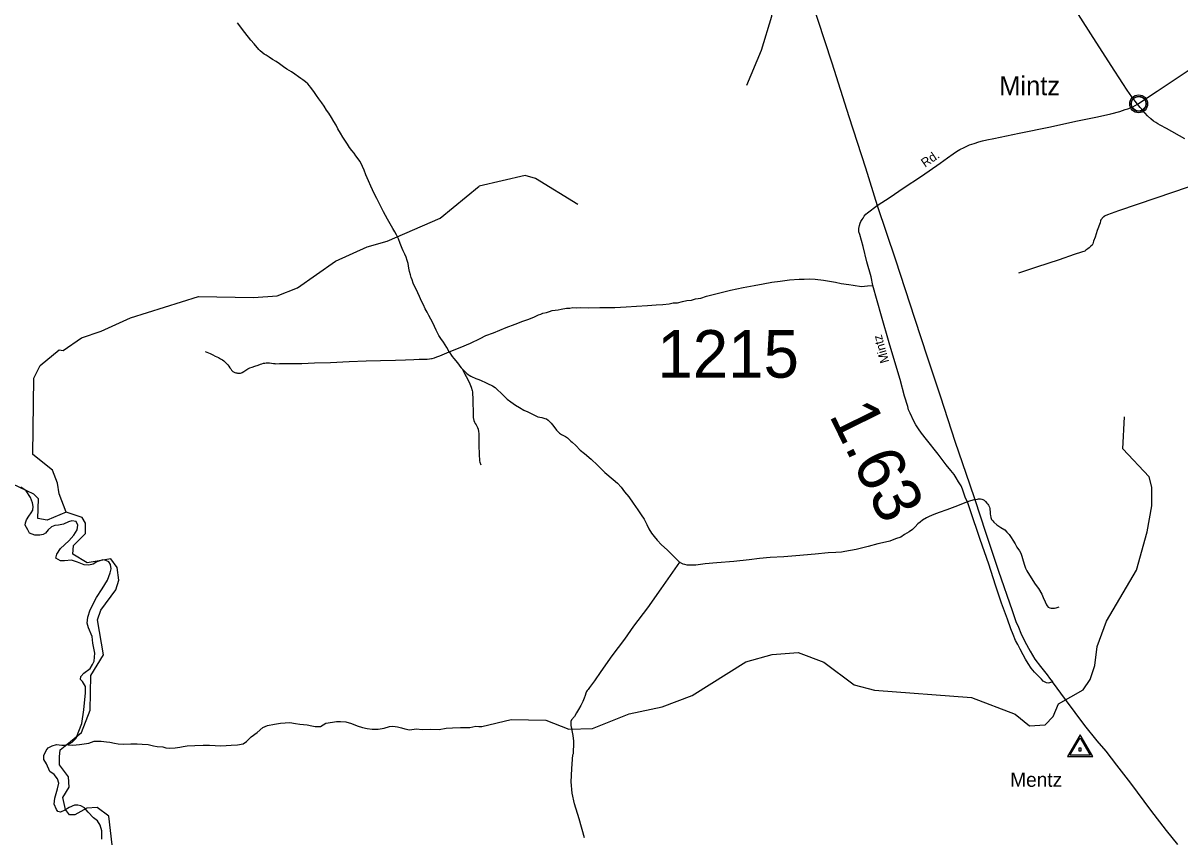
# Model space of a CAD drawing. Extents: x 2093524 to 2270757, y 289120 to 570408.
# Drawn here: x 2145218 to 2157372, y 409015 to 417566 of the extents above; entities that cross this region are included whole.
import ezdxf

# ---------------------------------------------------------------- set-up
doc = ezdxf.new("R2010")
doc.units = 0
for name, color, linetype in [('Exist Boundary Political CountyLine', 7, 'Continuous'), ('Exist Civil Demographics Community CELL', 7, 'Continuous'), ('Exist Civil Demographics Community Label', 7, 'Continuous'), ('Exist Hydrographic Creek Single Shore', 7, 'Continuous'), ('Exist Hydrographic Misc Water Feature', 7, 'Continuous'), ('Exist Road Non-System Type 51', 7, 'Continuous'), ('Exist Road Primary NC Attributed', 7, 'Continuous'), ('Exist Road Secondary Mileage Hundredths English Label', 7, 'Continuous'), ('Exist Road Secondary Type 51 Attributed', 7, 'Continuous'), ('Exist Road Secondary Type 51 Label', 7, 'Continuous'), ('Exist Road Secondary Type 51 Number Label', 7, 'Continuous'), ('Exist Survey Geodetic Marker CELL', 7, 'Continuous'), ('Exist Survey Geodetic Marker Label', 7, 'Continuous'), ('Exist Utilities Telephone Line', 7, 'Continuous')]:
    doc.layers.add(name, color=color, linetype=linetype)

msp = doc.modelspace()

# ---------------------------------------------------------------- linework, layer by layer
at = {"layer": 'Exist Boundary Political CountyLine'}
for points in [[(2145998, 409182), (2145957, 409214), (2145900, 409276), (2145863, 409319), (2145824, 409341), (2145792, 409347), (2145758, 409347), (2145702, 409324), (2145657, 409294), (2145612, 409274), (2145584, 409281), (2145568, 409304), (2145545, 409360), (2145551, 409423), (2145580, 409521), (2145592, 409581), (2145579, 409624), (2145545, 409672), (2145500, 409701), (2145464, 409783), (2145434, 409828), (2145434, 409869), (2145460, 409921), (2145480, 409950), (2145524, 409972), (2145568, 409985), (2145623, 409978), (2145658, 409980), (2145700, 409991), (2145733, 410011), (2145774, 410051), (2145804, 410127), (2145836, 410208), (2145855, 410350), (2145875, 410530), (2145875, 410594), (2145840, 410648), (2145821, 410669), (2145823, 410699), (2145857, 410734), (2145922, 410785), (2145948, 410826), (2145963, 410863), (2145971, 410944), (2145949, 411049), (2145944, 411122), (2145906, 411210), (2145890, 411262), (2145899, 411324), (2145921, 411401), (2145990, 411532), (2146048, 411620), (2146103, 411713), (2146134, 411788), (2146142, 411833), (2146136, 411876), (2146120, 411906), (2146088, 411919), (2146054, 411925), (2145992, 411906), (2145953, 411882), (2145910, 411869), (2145858, 411873), (2145788, 411901), (2145726, 411923), (2145654, 411917), (2145610, 411917), (2145562, 411944), (2145571, 411985), (2145612, 412045), (2145698, 412125), (2145752, 412185), (2145786, 412241), (2145793, 412290), (2145774, 412328), (2145728, 412335), (2145696, 412324), (2145643, 412301), (2145589, 412292), (2145552, 412288), (2145516, 412273), (2145482, 412240), (2145452, 412208), (2145428, 412191), (2145394, 412185), (2145340, 412187), (2145284, 412208), (2145269, 412243), (2145239, 412290), (2145243, 412316), (2145254, 412348), (2145278, 412384), (2145303, 412419), (2145320, 412447), (2145322, 412485), (2145318, 412526), (2145295, 412582), (2145250, 412650), (2145193, 412691)], [(2146046, 408991), (2146045, 409079), (2146026, 409139), (2145998, 409182)]]:
    msp.add_lwpolyline(points, dxfattribs=at)
at = {"layer": 'Exist Civil Demographics Community CELL'}
msp.add_lwpolyline([(2156862, 416730), (2156863, 416736), (2156864, 416742), (2156867, 416750), (2156870, 416755), (2156874, 416761), (2156877, 416766), (2156881, 416771), (2156886, 416775), (2156891, 416780), (2156897, 416783), (2156902, 416786), (2156907, 416789), (2156912, 416791), (2156918, 416793), (2156922, 416794), (2156927, 416795), (2156931, 416795), (2156938, 416796), (2156942, 416796), (2156948, 416795), (2156953, 416795), (2156957, 416794), (2156962, 416792), (2156968, 416790), (2156974, 416787), (2156981, 416784), (2156986, 416780), (2156991, 416776), (2156994, 416773), (2156998, 416769), (2157002, 416764), (2157005, 416759), (2157008, 416754), (2157011, 416749), (2157013, 416744), (2157014, 416739), (2157016, 416735), (2157017, 416729), (2157017, 416724), (2157018, 416718), (2157017, 416712), (2157017, 416706), (2157016, 416701), (2157014, 416695), (2157012, 416689), (2157010, 416684), (2157007, 416678), (2157004, 416673), (2157000, 416668), (2156996, 416663), (2156991, 416658), (2156986, 416654), (2156981, 416651), (2156976, 416648), (2156969, 416645), (2156962, 416642), (2156956, 416641), (2156950, 416639), (2156945, 416639), (2156941, 416639), (2156935, 416639), (2156931, 416639), (2156925, 416640), (2156919, 416641), (2156915, 416642), (2156910, 416644), (2156905, 416646), (2156901, 416649), (2156894, 416653), (2156889, 416657), (2156884, 416661), (2156879, 416666), (2156876, 416670), (2156873, 416674), (2156869, 416681), (2156867, 416685), (2156866, 416689), (2156863, 416697), (2156862, 416704), (2156861, 416709), (2156861, 416716), (2156861, 416720), (2156861, 416727)], close=True, dxfattribs=at)
for radius in [94.3, 76.7]:
    msp.add_circle((2156939, 416718), radius, dxfattribs=at)
at = {"layer": 'Exist Hydrographic Creek Single Shore'}
msp.add_line((2145639, 414126), (2145830, 414260), dxfattribs=at)
for points in [[(2152821, 416913), (2152977, 417280), (2153083, 417639), (2153074, 417905), (2153098, 417953), (2153073, 418062), (2152829, 418411), (2152619, 418635), (2152460, 418776), (2152143, 418898), (2152034, 419014), (2152032, 419264), (2151723, 419513), (2151547, 419762), (2151437, 420043), (2151377, 420320), (2151318, 420452), (2151284, 420617), (2151233, 420667), (2151147, 421233), (2151001, 421732), (2150776, 422081), (2150324, 422464), (2149980, 422851)], [(2151045, 415659), (2150602, 415933), (2150494, 415965), (2150010, 415853)], [(2145830, 414260), (2146038, 414328), (2146345, 414470), (2147061, 414692), (2147637, 414683), (2147886, 414701), (2148102, 414786), (2148500, 415063), (2148833, 415214), (2149042, 415275), (2149599, 415517), (2150010, 415853)], [(2145671, 412426), (2145595, 412618), (2145578, 412733), (2145528, 412869), (2145319, 413034), (2145332, 413834), (2145398, 413967), (2145597, 414134), (2145639, 414126)], [(2150036, 410175), (2150347, 410250), (2150709, 410243), (2150952, 410146), (2151201, 410154), (2151584, 410308), (2151933, 410383), (2152249, 410501), (2152813, 410854), (2153088, 410930), (2153363, 410951), (2153630, 410851), (2153948, 410611), (2154165, 410555), (2155181, 410479), (2155641, 410305), (2155791, 410181), (2155958, 410191), (2156041, 410281), (2156098, 410414), (2156355, 410560), (2156430, 410667), (2156479, 410817), (2156503, 411016), (2156601, 411283), (2156915, 411818), (2157029, 412220), (2157078, 412494), (2157077, 412688), (2157051, 412797), (2156774, 413094), (2156789, 413428)], [(2145676, 409984), (2145691, 409983), (2145741, 409980), (2145809, 409987), (2145859, 409991), (2145907, 410000), (2145966, 410019), (2146038, 410022), (2146094, 410014), (2146130, 410009), (2146177, 409999), (2146215, 409994), (2146273, 409990), (2146349, 409991), (2146417, 409992), (2146467, 409989), (2146531, 409984), (2146587, 409970), (2146627, 409965), (2146686, 409960), (2146718, 409952), (2146758, 409946), (2146816, 409951), (2146865, 409956), (2146898, 409966), (2146943, 409973), (2147021, 409976), (2147109, 409977), (2147177, 409980), (2147235, 409974), (2147294, 409971), (2147350, 409976), (2147405, 409977), (2147472, 409983), (2147531, 409992), (2147565, 410017), (2147614, 410065), (2147676, 410110), (2147735, 410163), (2147785, 410187), (2147859, 410200), (2147923, 410211), (2148021, 410216), (2148081, 410207), (2148125, 410200), (2148203, 410191), (2148253, 410183), (2148288, 410174), (2148342, 410176), (2148399, 410209), (2148467, 410222), (2148511, 410226), (2148551, 410227), (2148607, 410224), (2148667, 410206), (2148727, 410181), (2148782, 410164), (2148834, 410152), (2148886, 410147), (2148950, 410148), (2149012, 410157), (2149066, 410175), (2149104, 410180), (2149150, 410170), (2149194, 410159), (2149228, 410149), (2149276, 410140), (2149350, 410149), (2149410, 410144), (2149498, 410145), (2149590, 410144), (2149664, 410157), (2149730, 410162), (2149812, 410165), (2149856, 410165), (2149912, 410164), (2149944, 410172), (2149976, 410179), (2150006, 410175), (2150036, 410175)]]:
    msp.add_lwpolyline(points, dxfattribs=at)
at = {"layer": 'Exist Hydrographic Misc Water Feature'}
for points in [[(2145671, 412426), (2145472, 412342), (2145372, 412360), (2145379, 412567), (2145329, 412617), (2145037, 412757), (2144786, 412929), (2144704, 412947), (2144553, 412888), (2144528, 412856), (2144453, 412864), (2144253, 412979), (2144128, 412910), (2144137, 412627), (2144088, 412560), (2144005, 412502), (2143671, 412601), (2143354, 412774)], [(2145676, 409984), (2145832, 410110), (2145923, 410345), (2145930, 410712), (2146061, 410929), (2146001, 411295), (2146035, 411396), (2146191, 411612), (2146224, 411713), (2146207, 411845), (2146141, 411938), (2145890, 411894), (2145740, 411985), (2145748, 412077), (2145873, 412202), (2145873, 412311), (2145838, 412371), (2145671, 412426)], [(2145601, 409856), (2145607, 409928), (2145676, 409984)], [(2145636, 409429), (2145703, 409539), (2145695, 409647), (2145601, 409771), (2145601, 409856)], [(2149605, 404865), (2149524, 405343), (2149320, 405798), (2149038, 406174), (2148568, 406581), (2147909, 406957), (2147219, 407208), (2146592, 407428), (2146248, 407678), (2146122, 407851), (2146093, 408150), (2146105, 408799), (2146155, 408933), (2146120, 409232), (2145996, 409323), (2145887, 409315), (2145762, 409246), (2145704, 409247), (2145663, 409303), (2145636, 409429)]]:
    msp.add_lwpolyline(points, dxfattribs=at)
at = {"layer": 'Exist Road Non-System Type 51'}
msp.add_line((2155219, 412560), (2155140, 412535), dxfattribs=at)
for points in [[(2149694, 414111), (2149669, 414157), (2149635, 414215), (2149607, 414253), (2149587, 414284), (2149571, 414313), (2149559, 414339), (2149541, 414378), (2149523, 414417), (2149502, 414456), (2149482, 414494), (2149462, 414530), (2149443, 414565), (2149424, 414604), (2149405, 414645), (2149384, 414692), (2149365, 414731), (2149347, 414770), (2149331, 414803), (2149317, 414835), (2149305, 414867), (2149295, 414893), (2149287, 414922), (2149278, 414957), (2149272, 414990), (2149268, 415015), (2149262, 415041), (2149252, 415073), (2149242, 415105), (2149227, 415139), (2149211, 415174), (2149199, 415199), (2149179, 415250), (2149161, 415300), (2149140, 415342), (2149123, 415373), (2149102, 415408), (2149048, 415506), (2149006, 415583), (2148961, 415667), (2148933, 415723), (2148911, 415767), (2148889, 415813), (2148870, 415853), (2148848, 415907), (2148820, 415973), (2148800, 416021), (2148784, 416058), (2148772, 416085), (2148755, 416114), (2148739, 416140), (2148715, 416173), (2148695, 416198), (2148671, 416228), (2148647, 416259), (2148625, 416294), (2148605, 416324), (2148576, 416369), (2148554, 416409), (2148526, 416455), (2148506, 416495), (2148484, 416533), (2148458, 416575), (2148429, 416619), (2148407, 416652), (2148381, 416692), (2148355, 416730), (2148326, 416770), (2148301, 416806), (2148279, 416836), (2148253, 416874), (2148238, 416894), (2148226, 416907), (2148208, 416927), (2148184, 416949), (2148158, 416969), (2148135, 416984), (2148110, 417003), (2148072, 417029), (2148036, 417053), (2147989, 417082), (2147954, 417107), (2147911, 417137), (2147876, 417161), (2147839, 417184), (2147803, 417208), (2147771, 417228), (2147751, 417241), (2147728, 417256), (2147709, 417274), (2147694, 417289), (2147679, 417307), (2147660, 417330), (2147645, 417347), (2147612, 417387), (2147548, 417468), (2147470, 417570)], [(2157799, 415957), (2157121, 415727), (2156728, 415593), (2156612, 415553), (2156586, 415541), (2156576, 415535), (2156574, 415532), (2156568, 415529), (2156542, 415500), (2156538, 415488), (2156533, 415468), (2156503, 415386), (2156481, 415316), (2156466, 415274), (2156456, 415246), (2156450, 415234), (2156434, 415218), (2156420, 415204), (2156406, 415194), (2156384, 415180), (2156372, 415171), (2156340, 415159), (2156261, 415133), (2156103, 415080), (2155865, 415003), (2155676, 414938)], [(2149694, 414111), (2149811, 414156), (2149919, 414202), (2150021, 414253), (2150081, 414282), (2150161, 414313), (2150295, 414367), (2150387, 414402), (2150470, 414434), (2150530, 414455), (2150590, 414481), (2150632, 414499), (2150658, 414509), (2150680, 414518), (2150716, 414526), (2150748, 414534), (2150778, 414546), (2150809, 414550), (2150840, 414552), (2150870, 414559), (2150928, 414569), (2150961, 414571), (2150995, 414577), (2151035, 414575), (2151075, 414576), (2151161, 414574), (2151277, 414579), (2151359, 414579), (2151435, 414578), (2151553, 414586), (2151661, 414591), (2151777, 414598), (2151869, 414604), (2151941, 414608), (2152007, 414617), (2152049, 414625), (2152095, 414627), (2152145, 414640), (2152192, 414650), (2152241, 414656), (2152284, 414667), (2152338, 414677), (2152398, 414695), (2152524, 414728), (2152652, 414761), (2152782, 414787), (2152900, 414808), (2152993, 414826), (2153083, 414845), (2153173, 414856), (2153269, 414868), (2153371, 414877), (2153425, 414877), (2153481, 414879), (2153541, 414877), (2153627, 414866), (2153689, 414854), (2153755, 414845), (2153813, 414829), (2153895, 414819), (2153939, 414814), (2154027, 414798), (2154057, 414801), (2154089, 414805), (2154147, 414809)], [(2147129, 414116), (2147183, 414093), (2147211, 414079), (2147237, 414067), (2147270, 414052), (2147291, 414039), (2147311, 414027), (2147325, 414017), (2147341, 414004), (2147356, 413990), (2147369, 413976), (2147379, 413962), (2147391, 413944), (2147399, 413932), (2147404, 413926), (2147408, 413920), (2147414, 413912), (2147420, 413906), (2147427, 413901), (2147436, 413897), (2147443, 413895), (2147454, 413892), (2147462, 413890), (2147472, 413888), (2147482, 413886), (2147488, 413886), (2147493, 413886), (2147497, 413887), (2147502, 413888), (2147512, 413892), (2147520, 413896), (2147536, 413906), (2147558, 413919), (2147579, 413932), (2147599, 413943), (2147623, 413951), (2147653, 413961), (2147687, 413973), (2147713, 413981), (2147727, 413985), (2147745, 413991), (2147758, 413994), (2147771, 413995), (2147788, 413996), (2147807, 413996), (2147827, 413994), (2147849, 413990), (2147861, 413988), (2147874, 413987), (2147911, 413988), (2148053, 413988), (2148145, 413989), (2148278, 413996), (2148449, 414000), (2148644, 414009), (2148824, 414016), (2148972, 414020), (2149132, 414025), (2149234, 414029), (2149322, 414032), (2149378, 414034), (2149420, 414035), (2149442, 414036), (2149464, 414036), (2149486, 414038), (2149507, 414042), (2149516, 414043), (2149541, 414050), (2149566, 414059), (2149596, 414071), (2149694, 414111)], [(2149694, 414111), (2149726, 414063), (2149745, 414041), (2149764, 414016), (2149791, 413983), (2149808, 413960), (2149822, 413945), (2149830, 413934)], [(2149830, 413934), (2149852, 413890), (2149873, 413852), (2149893, 413813), (2149911, 413774), (2149925, 413739), (2149935, 413707), (2149939, 413691), (2149941, 413667), (2149943, 413627), (2149944, 413563), (2149945, 413499), (2149946, 413457), (2149948, 413421), (2149953, 413391), (2149959, 413371), (2149967, 413357), (2149977, 413343), (2149986, 413330), (2149993, 413317), (2149999, 413298), (2150003, 413275), (2150005, 413255), (2150006, 413129), (2150010, 413035), (2150012, 412967), (2150016, 412951), (2150027, 412924)], [(2149830, 413934), (2149881, 413884), (2149893, 413875), (2149906, 413866), (2149923, 413856), (2149943, 413847), (2149959, 413839), (2149976, 413832), (2149995, 413825), (2150023, 413813), (2150044, 413804), (2150062, 413798), (2150098, 413779), (2150150, 413753), (2150179, 413737), (2150203, 413713), (2150241, 413677), (2150271, 413646), (2150305, 413616), (2150343, 413588), (2150393, 413552), (2150435, 413526), (2150480, 413499), (2150522, 413481), (2150576, 413453), (2150626, 413429), (2150668, 413422), (2150698, 413412), (2150718, 413406), (2150736, 413392), (2150754, 413374), (2150766, 413362), (2150779, 413344), (2150793, 413326), (2150821, 413289), (2150853, 413257), (2150865, 413249), (2150875, 413243), (2150895, 413233), (2150915, 413223), (2150939, 413209), (2150971, 413174), (2150987, 413161), (2151024, 413128), (2151072, 413080), (2151116, 413042), (2151188, 412985), (2151253, 412921), (2151331, 412844), (2151418, 412770), (2151464, 412730), (2151502, 412689), (2151536, 412641), (2151581, 412587), (2151629, 412520), (2151677, 412450), (2151711, 412400), (2151744, 412354), (2151770, 412298), (2151792, 412253), (2151821, 412207), (2151847, 412171), (2151879, 412133), (2151927, 412085), (2151985, 412030), (2152052, 411964), (2152114, 411902)], [(2155140, 412535), (2155008, 412483), (2154924, 412450), (2154844, 412424), (2154786, 412401), (2154739, 412381), (2154711, 412367), (2154667, 412343), (2154643, 412321), (2154619, 412306), (2154589, 412272), (2154564, 412246), (2154526, 412220), (2154478, 412192), (2154440, 412166), (2154384, 412147), (2154326, 412123), (2154280, 412111), (2154200, 412094), (2154097, 412066), (2153969, 412035), (2153851, 412014), (2153817, 412008), (2153757, 412004), (2153677, 411999), (2153541, 411986), (2153337, 411969), (2153210, 411957), (2153068, 411952), (2152954, 411939), (2152846, 411926), (2152686, 411908), (2152508, 411893), (2152384, 411884), (2152286, 411869), (2152242, 411869), (2152218, 411869), (2152194, 411869), (2152172, 411877), (2152154, 411882), (2152140, 411889), (2152114, 411902)], [(2155219, 412560), (2155247, 412564), (2155257, 412566), (2155269, 412568), (2155277, 412566), (2155292, 412564), (2155301, 412560), (2155314, 412552), (2155321, 412546), (2155329, 412538), (2155343, 412521), (2155354, 412511), (2155360, 412501), (2155366, 412493), (2155372, 412479), (2155374, 412465), (2155374, 412453), (2155378, 412433), (2155380, 412407), (2155382, 412393), (2155386, 412371), (2155393, 412351), (2155405, 412335), (2155417, 412321), (2155449, 412295), (2155491, 412267), (2155533, 412242), (2155555, 412218), (2155579, 412194), (2155600, 412160), (2155616, 412134), (2155642, 412094), (2155660, 412058), (2155688, 412019), (2155700, 411995), (2155711, 411963), (2155725, 411915), (2155739, 411871), (2155751, 411837), (2155763, 411811), (2155808, 411738), (2155852, 411670), (2155887, 411624), (2155921, 411564), (2155937, 411530), (2155955, 411486), (2155971, 411452), (2155977, 411442), (2155988, 411430), (2156007, 411421), (2156020, 411417), (2156038, 411417), (2156054, 411419), (2156073, 411423), (2156103, 411431)], [(2152114, 411902), (2151920, 411621), (2151777, 411421), (2151632, 411230), (2151535, 411093), (2151404, 410917), (2151289, 410754), (2151222, 410656), (2151170, 410585), (2151154, 410565), (2151144, 410553), (2151136, 410543), (2151130, 410525), (2151124, 410501), (2151113, 410471), (2151099, 410439), (2151077, 410395), (2151053, 410353), (2151033, 410317), (2151010, 410281), (2150980, 410244), (2150974, 410228), (2150972, 410219), (2150972, 410205), (2150974, 410184), (2150978, 410155), (2150985, 410115), (2150993, 410079), (2150999, 410019), (2151002, 409967), (2150998, 409931), (2150998, 409905), (2150996, 409883)], [(2151117, 409005), (2151060, 409203), (2151011, 409362), (2150988, 409474), (2150977, 409592), (2150983, 409730), (2150994, 409882)]]:
    msp.add_lwpolyline(points, dxfattribs=at)
at = {"layer": 'Exist Road Primary NC Attributed'}
for points in [[(2156925, 416716), (2156867, 416792), (2156817, 416861), (2156772, 416931), (2156651, 417119), (2156435, 417455), (2156227, 417782), (2156038, 418087), (2155834, 418431), (2155610, 418824), (2155404, 419180), (2155333, 419318)], [(2157423, 416349), (2157233, 416458), (2157166, 416492), (2157139, 416509), (2157120, 416521), (2157096, 416537), (2157066, 416561), (2157032, 416593), (2157006, 416620), (2156982, 416648), (2156956, 416678), (2156939, 416698), (2156925, 416716)]]:
    msp.add_lwpolyline(points, dxfattribs=at)
at = {"layer": 'Exist Road Secondary Type 51 Attributed'}
for points in [[(2156925, 416716), (2157135, 416851), (2157511, 417103)], [(2156034, 410643), (2156002, 410633), (2155988, 410631), (2155970, 410633), (2155958, 410639), (2155934, 410650), (2155918, 410672), (2155886, 410704), (2155843, 410746), (2155811, 410788), (2155779, 410836), (2155749, 410883), (2155724, 410927), (2155694, 410987), (2155668, 411037), (2155646, 411077), (2155621, 411143), (2155597, 411202), (2155560, 411304), (2155499, 411472), (2155435, 411659), (2155365, 411881), (2155274, 412140), (2155168, 412452), (2155140, 412535), (2155121, 412573), (2155109, 412607), (2155087, 412667), (2155073, 412703), (2155047, 412747), (2155022, 412788), (2155000, 412822), (2154966, 412866), (2154918, 412924), (2154831, 413037), (2154708, 413191), (2154656, 413258), (2154626, 413302), (2154597, 413346), (2154577, 413384), (2154537, 413466), (2154522, 413503), (2154512, 413539), (2154480, 413645), (2154433, 413821), (2154378, 414008), (2154317, 414206), (2154237, 414488), (2154147, 414809), (2154127, 414901), (2154084, 415058), (2154043, 415220), (2154008, 415346), (2154000, 415374), (2154000, 415390), (2154000, 415404), (2154000, 415408), (2154006, 415440), (2154013, 415464), (2154021, 415482), (2154033, 415502), (2154043, 415518), (2154055, 415536), (2154071, 415558), (2154089, 415574), (2154190, 415651), (2154328, 415738), (2154465, 415833), (2154656, 415959), (2154853, 416096), (2154931, 416151), (2154989, 416191), (2155025, 416217), (2155061, 416238), (2155106, 416260), (2155162, 416286), (2155212, 416301), (2155258, 416317), (2155298, 416329), (2155342, 416339), (2155418, 416355), (2155683, 416411), (2156013, 416477), (2156279, 416536), (2156508, 416582), (2156646, 416612), (2156740, 416637), (2156796, 416657), (2156824, 416665), (2156836, 416670), (2156858, 416680), (2156877, 416688), (2156925, 416716)]]:
    msp.add_lwpolyline(points, dxfattribs=at)
at = {"layer": 'Exist Survey Geodetic Marker CELL'}
for points in [[(2156457, 409861), (2156323, 410087), (2156190, 409861)], [(2156431, 409873), (2156216, 409873), (2156323, 410055)], [(2156336, 409920), (2156336, 409948), (2156311, 409948), (2156311, 409920)]]:
    msp.add_lwpolyline(points, close=True, dxfattribs=at)
at = {"layer": 'Exist Utilities Telephone Line'}
for points in [[(2152937, 419447), (2153124, 418922), (2153267, 418489), (2153407, 418076), (2153564, 417607), (2153714, 417150), (2153895, 416585), (2154068, 416044), (2154190, 415651)], [(2154190, 415651), (2154383, 415078), (2154585, 414464), (2154719, 414049), (2154853, 413649), (2155012, 413162), (2155161, 412723), (2155219, 412560)], [(2155219, 412560), (2155329, 412218), (2155466, 411807), (2155610, 411394), (2155648, 411278), (2155675, 411217), (2155701, 411155), (2155744, 411069), (2155798, 410967), (2155849, 410884), (2155907, 410804), (2155978, 410717), (2156002, 410681), (2156034, 410643)], [(2157349, 408934), (2157230, 409081), (2157067, 409296), (2156857, 409579), (2156710, 409768), (2156596, 409914), (2156504, 410024), (2156373, 410185), (2156169, 410460), (2156034, 410643)]]:
    msp.add_lwpolyline(points, dxfattribs=at)

# ---------------------------------------------------------------- texts
at = {"layer": 'Exist Civil Demographics Community Label'}
msp.add_text('Mintz', height=200, dxfattribs=at).set_placement((2155474, 416808))
at = {"layer": 'Exist Road Secondary Mileage Hundredths English Label'}
msp.add_text('1.63', height=500, rotation=296.2518, dxfattribs=at).set_placement((2153681, 413447))
at = {"layer": 'Exist Road Secondary Type 51 Label'}
for s, rotation, p in [('Rd.', 34.8039, (2154694, 416046)), ('Mintz', 105.8099, (2154319, 414008))]:
    msp.add_text(s, height=95, rotation=rotation, dxfattribs=at).set_placement(p)
at = {"layer": 'Exist Road Secondary Type 51 Number Label'}
msp.add_text('1215', height=500, dxfattribs=at).set_placement((2151882, 413840))
at = {"layer": 'Exist Survey Geodetic Marker Label'}
msp.add_text('Mentz', height=150, dxfattribs=at).set_placement((2155589, 409541))

doc.saveas('drawing.dxf')
